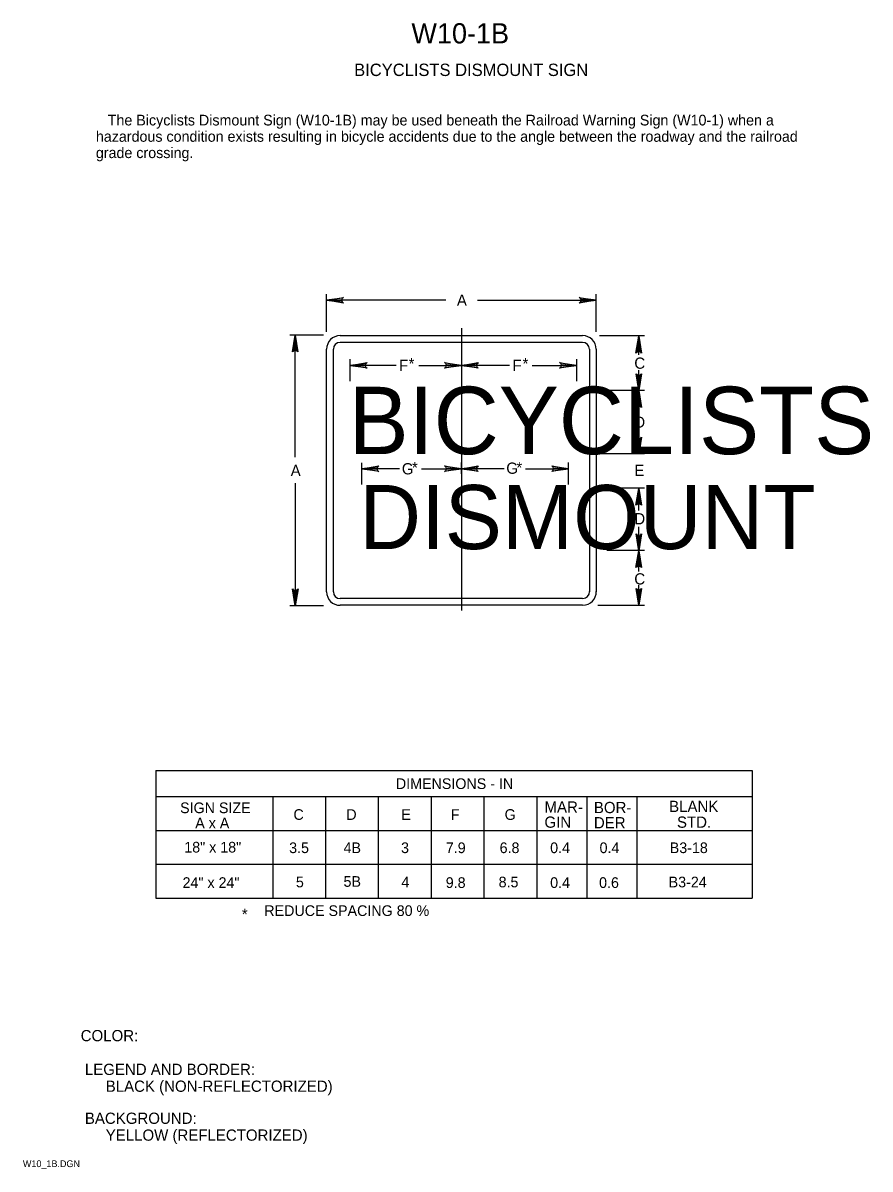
# Model space of a CAD drawing. Extents: x 0.013 to 0.201, y 0.004 to 0.259.
import ezdxf

# ---------------------------------------------------------------- set-up
doc = ezdxf.new("R2010")
doc.units = 0
for name, color, linetype in [('1', 7, 'Continuous'), ('11', 7, 'Continuous'), ('12', 7, 'Continuous'), ('2', 7, 'Continuous'), ('3', 7, 'Continuous')]:
    doc.layers.add(name, color=color, linetype=linetype)

# ---------------------------------------------------------------- blocks, each defined once
blk = doc.blocks.new('RARROW')
at = {"layer": '3'}
for p, q in [((-2.156, 0.285), (-2.2665, 0.384625)), ((-2.2665, 0.384625), (0, 0)), ((0, 0), (-2.2665, -0.379125)), ((-2.156, 0.285), (-2.075625, 0.12075)), ((0, 0), (-2.156, 0.285)), ((-2.14975, -0.2705), (0, 0)), ((-2.075625, 0.12075), (0, 0)), ((0, 0), (-2.074, -0.108)), ((-2.2665, -0.379125), (-2.14975, -0.2705)), ((-2.074, -0.108), (-2.14975, -0.2705))]:
    blk.add_line(p, q, dxfattribs=at)

msp = doc.modelspace()

# ---------------------------------------------------------------- linework, layer by layer
at = {"layer": '1'}
msp.add_line((0.11025, 0.191), (0.11025, 0.12825), dxfattribs=at)
at = {"layer": '11'}
for p, q in [((0.08325, 0.18938), (0.13725, 0.18938)), ((0.08025, 0.13237), (0.08025, 0.18637)), ((0.08175, 0.13237), (0.08175, 0.18637)), ((0.08325, 0.18788), (0.13725, 0.18788)), ((0.13875, 0.18637), (0.13875, 0.13237)), ((0.14025, 0.18637), (0.14025, 0.13237)), ((0.13725, 0.13087), (0.08325, 0.13087)), ((0.13725, 0.12937), (0.08325, 0.12937))]:
    msp.add_line(p, q, dxfattribs=at)
for centre, radius, start, end in [((0.08325, 0.18637), 0.003, 90, 180), ((0.13725, 0.18637), 0.003, 0, 90), ((0.08325, 0.18637), 0.0015, 90, 180), ((0.13725, 0.18637), 0.0015, 0, 90), ((0.08325, 0.13237), 0.003, 180, 270), ((0.08325, 0.13237), 0.0015, 180, 270), ((0.13729, 0.13242), 0.003, 270, 0), ((0.13729, 0.13242), 0.0015, 270, 0)]:
    msp.add_arc(centre, radius, start, end, dxfattribs=at)
at = {"layer": '3'}
for p, q in [((0.08025, 0.19025), (0.08025, 0.19862)), ((0.10682, 0.19725), (0.08025, 0.19725)), ((0.11384, 0.19725), (0.14025, 0.19725)), ((0.14029, 0.19025), (0.14029, 0.19862)), ((0.07954, 0.1895), (0.07204, 0.1895)), ((0.07325, 0.16233), (0.07325, 0.1895)), ((0.141, 0.18938), (0.151, 0.18938)), ((0.14979, 0.18512), (0.14979, 0.18937)), ((0.0855, 0.17925), (0.0855, 0.18412)), ((0.13592, 0.17925), (0.13592, 0.18412)), ((0.09575, 0.18275), (0.0855, 0.18275)), ((0.10079, 0.18275), (0.11025, 0.18275)), ((0.121, 0.18275), (0.11025, 0.18275)), ((0.12604, 0.18275), (0.13587, 0.18275)), ((0.14979, 0.172), (0.14979, 0.18171)), ((0.14225, 0.17725), (0.151, 0.17725)), ((0.14979, 0.16312), (0.14979, 0.16852)), ((0.08811, 0.15622), (0.08811, 0.16109)), ((0.11029, 0.15862), (0.11029, 0.16112)), ((0.13412, 0.15624), (0.13412, 0.16111)), ((0.14125, 0.16312), (0.151, 0.16312)), ((0.09644, 0.15975), (0.08812, 0.15975)), ((0.10138, 0.15975), (0.11025, 0.15975)), ((0.11976, 0.15975), (0.11025, 0.15975)), ((0.12454, 0.15975), (0.13412, 0.15975)), ((0.07325, 0.15657), (0.07325, 0.12925)), ((0.14113, 0.1555), (0.151, 0.1555)), ((0.14979, 0.1505), (0.14979, 0.1555)), ((0.14979, 0.13687), (0.14979, 0.14684)), ((0.14263, 0.14163), (0.151, 0.14163)), ((0.14979, 0.12937), (0.14979, 0.13385)), ((0.07957, 0.12926), (0.07207, 0.12926)), ((0.14062, 0.12937), (0.151, 0.12937)), ((0.04225, 0.09262), (0.175, 0.09262)), ((0.04225, 0.09262), (0.04225, 0.06425)), ((0.175, 0.09262), (0.175, 0.06425)), ((0.175, 0.08675), (0.04225, 0.08675)), ((0.08, 0.08675), (0.08, 0.06425)), ((0.09175, 0.08675), (0.09175, 0.06425)), ((0.1035, 0.08675), (0.1035, 0.06425)), ((0.11525, 0.08675), (0.11525, 0.06425)), ((0.06829, 0.08669), (0.06829, 0.06419)), ((0.12704, 0.08669), (0.12704, 0.06419)), ((0.13817, 0.08669), (0.13817, 0.06419)), ((0.14929, 0.08669), (0.14929, 0.06419)), ((0.04225, 0.07925), (0.175, 0.07925)), ((0.04225, 0.07175), (0.175, 0.07175)), ((0.04225, 0.06425), (0.175, 0.06425))]:
    msp.add_line(p, q, dxfattribs=at)

# ---------------------------------------------------------------- block references
at = {"layer": '3', "xscale": 0.0016545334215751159, "yscale": 0.0016366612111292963}
for p, rotation in [((0.08025, 0.19725), 180), ((0.07325, 0.1895), 90), ((0.14975, 0.18925), 90), ((0.0855, 0.18275), 180), ((0.11025, 0.18275), 180), ((0.14975, 0.17713), -90), ((0.14975, 0.17713), 90), ((0.14975, 0.163), -90), ((0.08812, 0.15975), 180), ((0.11025, 0.15975), 180), ((0.14975, 0.15538), 90), ((0.14975, 0.1415), -90), ((0.14975, 0.1415), 90), ((0.07325, 0.12925), -90), ((0.14975, 0.12937), -90)]:
    msp.add_blockref('RARROW', p, dxfattribs=dict(at, rotation=rotation))
for p in [(0.14025, 0.19725), (0.11025, 0.18275), (0.13587, 0.18275), (0.11025, 0.15975), (0.13412, 0.15975)]:
    msp.add_blockref('RARROW', p, dxfattribs=at)

# ---------------------------------------------------------------- texts
at = {"layer": '1'}
for s, height, p in [('W10-1B', 0.0045, (0.09913, 0.25438)), ('BICYCLISTS DISMOUNT SIGN', 0.0027503, (0.08638, 0.24713)), ('COLOR:', 0.0025, (0.0255, 0.03238)), (' LEGEND AND BORDER:', 0.0024998, (0.0255, 0.02488)), ('      BLACK (NON-REFLECTORIZED)', 0.0024998, (0.0255, 0.02113)), (' BACKGROUND:', 0.0024998, (0.0255, 0.014)), ('      YELLOW (REFLECTORIZED)', 0.0024998, (0.0255, 0.01025)), ('W10_1B.DGN', 0.0015, (0.01263, 0.00438))]:
    msp.add_text(s, height=height, dxfattribs=at).set_placement(p)
at = {"layer": '12'}
for s, height, p in [('BICYCLISTS', 0.015, (0.08513, 0.163)), ('DISMOUNT', 0.014249, (0.0875, 0.14188))]:
    msp.add_text(s, height=height, dxfattribs=at).set_placement(p)
at = {"layer": '2'}
for s, height, p in [('   The Bicyclists Dismount Sign (W10-1B) may be used beneath the Railroad Warning Sign (W10-1) when a ', 0.00237525, (0.02888, 0.23613)), ('hazardous condition exists resulting in bicycle accidents due to the angle between the roadway and the railroad ', 0.00237525, (0.02888, 0.2325)), ('grade crossing.', 0.0023752, (0.02888, 0.22887))]:
    msp.add_text(s, height=height, dxfattribs=at).set_placement(p)
at = {"layer": '3'}
for s, height, p in [('A', 0.0025, (0.10925, 0.196)), ('F', 0.0025, (0.09638, 0.1815)), ('*', 0.0025, (0.0985, 0.18188)), ('F', 0.0025, (0.12162, 0.1815)), ('*', 0.0025, (0.12387, 0.18188)), ('C', 0.0025, (0.14875, 0.182)), ('D', 0.0025, (0.14875, 0.16887)), ('G', 0.0025, (0.097, 0.1585)), ('*', 0.0025, (0.09925, 0.15875)), ('G', 0.0025, (0.12025, 0.15863)), ('*', 0.0025, (0.1225, 0.15875)), ('A', 0.0025, (0.07225, 0.15813)), ('E', 0.0025, (0.14875, 0.15813)), ('D', 0.0025, (0.14875, 0.14738)), ('C', 0.0025, (0.14875, 0.134)), ('DIMENSIONS - IN', 0.0023752, (0.09567, 0.0885)), ('SIGN SIZE', 0.002375, (0.04763, 0.08313)), ('MAR-', 0.0025, (0.12875, 0.08325)), ('BOR-', 0.0025, (0.13975, 0.08313)), ('BLANK', 0.0025, (0.1565, 0.08338)), ('A x A', 0.002375, (0.051, 0.07975)), ('C', 0.00238, (0.07287, 0.08163)), ('D', 0.00238, (0.08463, 0.08163)), ('E', 0.00238, (0.09688, 0.08163)), ('F', 0.00238, (0.10787, 0.08163)), ('G', 0.00238, (0.11988, 0.08163)), ('GIN', 0.0025, (0.12875, 0.07988)), ('DER', 0.0025, (0.13975, 0.07975)), ('STD.', 0.0025, (0.15825, 0.07988)), ('18" x 18"', 0.002375, (0.04856, 0.07437)), ('3.5', 0.002375, (0.07191, 0.07424)), ('4B', 0.002375, (0.08402, 0.07424)), ('3', 0.00238, (0.09682, 0.07424)), ('7.9', 0.002375, (0.10679, 0.07424)), ('6.8', 0.002375, (0.11877, 0.07424)), ('0.4', 0.002375, (0.13002, 0.07424)), ('0.4', 0.002375, (0.14102, 0.07424)), ('B3-18', 0.002375, (0.15664, 0.07424)), ('24" x 24"', 0.002375, (0.04818, 0.06649)), ('5', 0.00238, (0.07341, 0.06662)), ('5B', 0.002375, (0.08402, 0.06674)), ('4', 0.00238, (0.0969, 0.06662)), ('9.8', 0.002375, (0.10677, 0.06649)), ('8.5', 0.002375, (0.11854, 0.06662)), ('0.4', 0.002375, (0.13002, 0.06649)), ('0.6', 0.002375, (0.14091, 0.06649)), ('B3-24', 0.002375, (0.1564, 0.06662)), ('*', 0.0025, (0.06137, 0.05938)), ('REDUCE SPACING 80 %', 0.0023752, (0.06638, 0.06025))]:
    msp.add_text(s, height=height, dxfattribs=at).set_placement(p)

doc.saveas('drawing.dxf')
